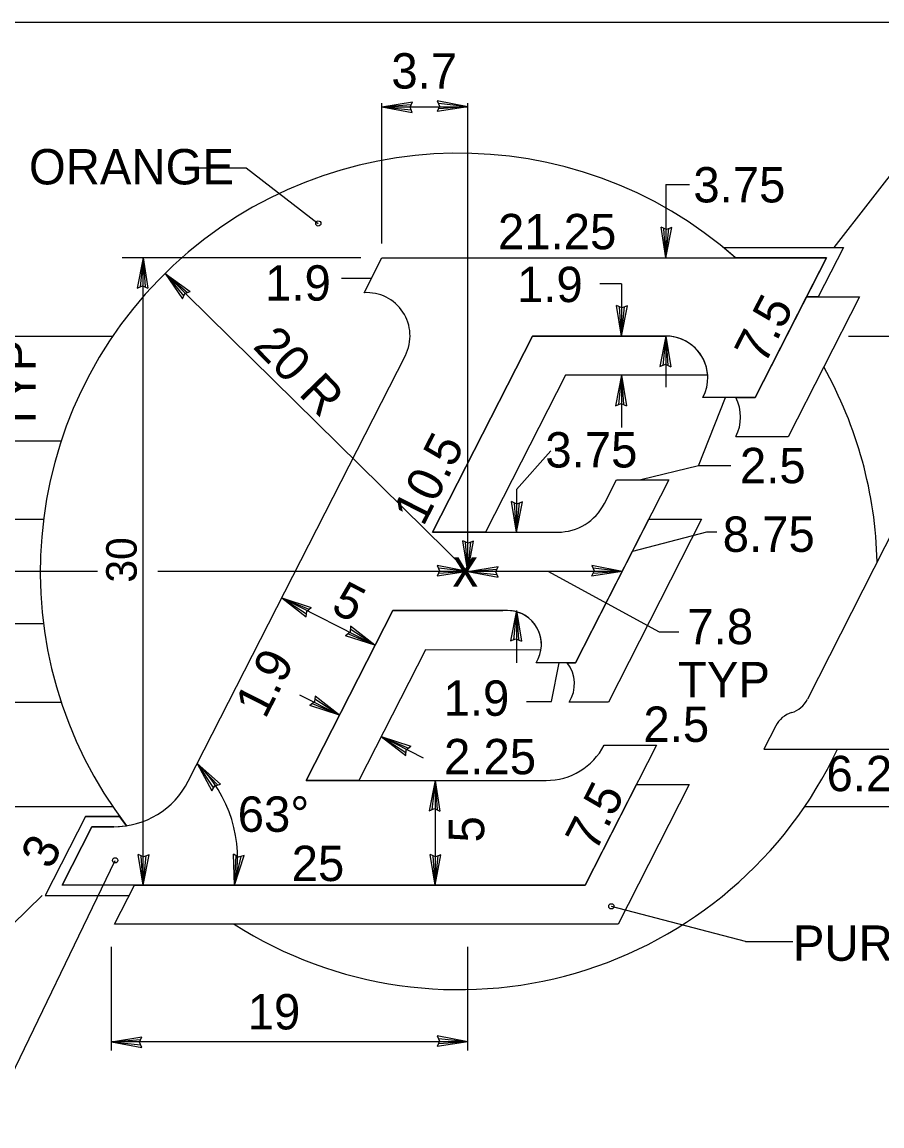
# Model space of a CAD drawing. Extents: x 10268197 to 10269179, y 2141503 to 2142677.
# Drawn here: x 10268467.86 to 10268484.88, y 2142149.08 to 2142170.94 of the extents above; entities that cross this region are included whole.
import ezdxf

# ---------------------------------------------------------------- set-up
doc = ezdxf.new("R2010")
doc.units = 0
for name, color, linetype in [('1', 7, 'Continuous'), ('2', 7, 'Continuous'), ('21', 7, 'Continuous'), ('3', 7, 'Continuous')]:
    doc.layers.add(name, color=color, linetype=linetype)

msp = doc.modelspace()

# ---------------------------------------------------------------- linework, layer by layer
at = {"layer": '1'}
for p, q in [((10268466.124, 2142170.939), (10268491.278, 2142170.939)), ((10268474.985, 2142169.263), (10268475.59, 2142169.359)), ((10268474.985, 2142166.558), (10268474.985, 2142169.336)), ((10268474.985, 2142169.263), (10268475.565, 2142169.304)), ((10268474.985, 2142169.263), (10268476.683, 2142169.263)), ((10268474.985, 2142169.263), (10268475.586, 2142169.147)), ((10268474.985, 2142169.263), (10268475.563, 2142169.203)), ((10268475.542, 2142169.254), (10268475.59, 2142169.359)), ((10268475.586, 2142169.147), (10268475.542, 2142169.254)), ((10268476.683, 2142160.063), (10268476.683, 2142169.336)), ((10268483.936, 2142166.474), (10268485.961, 2142169.092)), ((10268471.362, 2142168.055), (10268472.299, 2142168.055)), ((10268472.299, 2142168.055), (10268473.726, 2142166.952)), ((10268480.605, 2142167.724), (10268480.605, 2142166.274)), ((10268480.605, 2142167.724), (10268481.073, 2142167.724)), ((10268480.605, 2142166.274), (10268480.509, 2142166.879)), ((10268480.614, 2142166.831), (10268480.509, 2142166.879)), ((10268480.605, 2142166.274), (10268480.565, 2142166.854)), ((10268480.605, 2142166.274), (10268480.722, 2142166.875)), ((10268480.605, 2142166.274), (10268480.665, 2142166.852)), ((10268480.722, 2142166.875), (10268480.614, 2142166.831)), ((10268474.571, 2142166.274), (10268469.846, 2142166.274)), ((10268470.259, 2142166.274), (10268470.143, 2142165.672)), ((10268470.259, 2142166.274), (10268470.199, 2142165.695)), ((10268470.259, 2142153.853), (10268470.259, 2142166.274)), ((10268470.259, 2142166.274), (10268470.355, 2142165.668)), ((10268470.259, 2142166.274), (10268470.3, 2142165.694)), ((10268476.683, 2142160.063), (10268470.694, 2142165.963)), ((10268470.694, 2142165.963), (10268471.193, 2142165.607)), ((10268470.694, 2142165.963), (10268471.041, 2142165.457)), ((10268470.694, 2142165.963), (10268471.065, 2142165.514)), ((10268470.694, 2142165.963), (10268471.136, 2142165.585)), ((10268474.774, 2142165.86), (10268474.184, 2142165.86)), ((10268479.726, 2142165.756), (10268479.295, 2142165.756)), ((10268479.726, 2142165.756), (10268479.726, 2142164.721)), ((10268470.143, 2142165.672), (10268470.25, 2142165.717)), ((10268470.25, 2142165.717), (10268470.355, 2142165.668)), ((10268471.041, 2142165.457), (10268471.085, 2142165.565)), ((10268471.085, 2142165.565), (10268471.193, 2142165.607)), ((10268479.726, 2142164.721), (10268479.629, 2142165.326)), ((10268479.735, 2142165.278), (10268479.629, 2142165.326)), ((10268479.726, 2142164.721), (10268479.685, 2142165.301)), ((10268479.726, 2142164.721), (10268479.842, 2142165.323)), ((10268479.726, 2142164.721), (10268479.786, 2142165.299)), ((10268479.842, 2142165.323), (10268479.735, 2142165.278)), ((10268482.372, 2142163.504), (10268483.388, 2142165.497)), ((10268484.433, 2142165.497), (10268483.023, 2142162.73)), ((10268483.388, 2142165.497), (10268484.433, 2142165.497)), ((10268475.989, 2142160.84), (10268477.966, 2142164.721)), ((10268477.966, 2142164.721), (10268480.605, 2142164.721)), ((10268480.605, 2142164.721), (10268480.488, 2142164.119)), ((10268480.605, 2142164.721), (10268480.544, 2142164.142)), ((10268480.605, 2142164.721), (10268480.701, 2142164.115)), ((10268480.605, 2142164.721), (10268480.646, 2142164.142)), ((10268480.605, 2142164.721), (10268480.605, 2142163.71)), ((10268480.488, 2142164.119), (10268480.595, 2142164.164)), ((10268480.595, 2142164.164), (10268480.701, 2142164.115)), ((10268478.617, 2142163.945), (10268477.035, 2142160.84)), ((10268481.432, 2142163.945), (10268478.617, 2142163.945)), ((10268479.726, 2142163.945), (10268479.609, 2142163.343)), ((10268479.726, 2142163.945), (10268479.665, 2142163.366)), ((10268479.726, 2142163.945), (10268479.726, 2142162.91)), ((10268479.726, 2142163.945), (10268479.822, 2142163.339)), ((10268479.726, 2142163.945), (10268479.766, 2142163.365)), ((10268479.609, 2142163.343), (10268479.717, 2142163.387)), ((10268479.717, 2142163.387), (10268479.822, 2142163.339)), ((10268481.25, 2142162.153), (10268481.781, 2142163.507)), ((10268481.987, 2142163.504), (10268482.372, 2142163.504)), ((10268483.023, 2142162.73), (10268481.988, 2142162.73)), ((10268478.33, 2142162.452), (10268477.647, 2142161.682)), ((10268481.25, 2142162.153), (10268480.111, 2142161.875)), ((10268481.893, 2142162.153), (10268481.25, 2142162.153)), ((10268477.647, 2142161.682), (10268477.647, 2142160.84)), ((10268477.647, 2142160.84), (10268477.551, 2142161.444)), ((10268477.657, 2142161.397), (10268477.551, 2142161.444)), ((10268477.647, 2142160.84), (10268477.607, 2142161.419)), ((10268477.647, 2142160.84), (10268477.764, 2142161.441)), ((10268477.647, 2142160.84), (10268477.708, 2142161.418)), ((10268477.764, 2142161.441), (10268477.657, 2142161.397)), ((10268478.816, 2142158.252), (10268480.267, 2142161.098)), ((10268481.312, 2142161.098), (10268479.466, 2142157.475)), ((10268480.267, 2142161.098), (10268481.312, 2142161.098)), ((10268477.035, 2142160.84), (10268475.989, 2142160.84)), ((10268481.405, 2142160.84), (10268479.942, 2142160.46)), ((10268481.611, 2142160.84), (10268481.405, 2142160.84)), ((10268476.683, 2142160.063), (10268476.586, 2142160.668)), ((10268476.692, 2142160.621), (10268476.586, 2142160.668)), ((10268476.683, 2142160.063), (10268476.642, 2142160.643)), ((10268476.683, 2142160.063), (10268476.799, 2142160.664)), ((10268476.683, 2142160.063), (10268476.743, 2142160.641)), ((10268476.799, 2142160.664), (10268476.692, 2142160.621)), ((10268469.356, 2142160.063), (10268462.621, 2142160.063)), ((10268476.683, 2142160.063), (10268470.549, 2142160.063)), ((10268476.125, 2142160.073), (10268476.077, 2142159.967)), ((10268476.683, 2142160.063), (10268476.077, 2142159.967)), ((10268476.683, 2142160.063), (10268476.081, 2142160.18)), ((10268476.081, 2142160.18), (10268476.125, 2142160.073)), ((10268476.683, 2142160.063), (10268476.103, 2142160.023)), ((10268476.683, 2142160.063), (10268476.104, 2142160.124)), ((10268476.683, 2142160.063), (10268477.287, 2142160.159)), ((10268476.683, 2142160.063), (10268477.262, 2142160.104)), ((10268479.739, 2142160.063), (10268476.683, 2142160.063)), ((10268476.683, 2142160.063), (10268477.284, 2142159.947)), ((10268476.683, 2142160.063), (10268477.261, 2142160.003)), ((10268477.239, 2142160.054), (10268477.287, 2142160.159)), ((10268477.284, 2142159.947), (10268477.239, 2142160.054)), ((10268480.479, 2142158.858), (10268478.275, 2142160.063)), ((10268479.182, 2142160.073), (10268479.134, 2142159.967)), ((10268479.739, 2142160.063), (10268479.134, 2142159.967)), ((10268479.739, 2142160.063), (10268479.137, 2142160.18)), ((10268479.137, 2142160.18), (10268479.182, 2142160.073)), ((10268479.739, 2142160.063), (10268479.159, 2142160.023)), ((10268479.739, 2142160.063), (10268479.161, 2142160.124)), ((10268474.848, 2142158.599), (10268473.003, 2142159.54)), ((10268473.003, 2142159.54), (10268473.586, 2142159.35)), ((10268473.003, 2142159.54), (10268473.486, 2142159.162)), ((10268473.003, 2142159.54), (10268473.491, 2142159.223)), ((10268473.003, 2142159.54), (10268473.538, 2142159.313)), ((10268473.484, 2142155.923), (10268475.198, 2142159.287)), ((10268473.486, 2142159.162), (10268473.496, 2142159.278)), ((10268473.496, 2142159.278), (10268473.586, 2142159.35)), ((10268475.198, 2142159.287), (10268477.372, 2142159.28)), ((10268477.647, 2142159.287), (10268477.531, 2142158.685)), ((10268477.647, 2142159.287), (10268477.587, 2142158.708)), ((10268477.647, 2142159.287), (10268477.744, 2142158.681)), ((10268477.647, 2142159.287), (10268477.688, 2142158.707)), ((10268477.647, 2142159.287), (10268477.647, 2142158.252)), ((10268474.365, 2142158.976), (10268474.356, 2142158.861)), ((10268474.848, 2142158.599), (10268474.365, 2142158.976)), ((10268474.356, 2142158.861), (10268474.265, 2142158.788)), ((10268474.848, 2142158.599), (10268474.265, 2142158.788)), ((10268474.848, 2142158.599), (10268474.313, 2142158.826)), ((10268474.848, 2142158.599), (10268474.36, 2142158.916)), ((10268480.864, 2142158.858), (10268480.479, 2142158.858)), ((10268477.531, 2142158.685), (10268477.638, 2142158.73)), ((10268477.638, 2142158.73), (10268477.744, 2142158.681)), ((10268475.847, 2142158.509), (10268474.53, 2142155.923)), ((10268478.133, 2142158.501), (10268475.847, 2142158.509)), ((10268478.339, 2142157.489), (10268478.495, 2142158.252)), ((10268478.653, 2142158.252), (10268478.816, 2142158.252)), ((10268474.143, 2142157.216), (10268473.362, 2142157.615)), ((10268473.651, 2142157.478), (10268473.56, 2142157.405)), ((10268474.143, 2142157.216), (10268473.609, 2142157.443)), ((10268473.661, 2142157.594), (10268473.651, 2142157.478)), ((10268474.143, 2142157.216), (10268473.656, 2142157.533)), ((10268474.143, 2142157.216), (10268473.661, 2142157.594)), ((10268477.844, 2142157.489), (10268478.339, 2142157.489)), ((10268479.466, 2142157.475), (10268478.69, 2142157.475)), ((10268474.143, 2142157.216), (10268473.56, 2142157.405)), ((10268475.805, 2142156.368), (10268474.973, 2142156.792)), ((10268474.973, 2142156.792), (10268475.556, 2142156.603)), ((10268474.973, 2142156.792), (10268475.456, 2142156.416)), ((10268474.973, 2142156.792), (10268475.461, 2142156.476)), ((10268474.973, 2142156.792), (10268475.508, 2142156.566)), ((10268475.465, 2142156.531), (10268475.556, 2142156.603)), ((10268475.456, 2142156.416), (10268475.465, 2142156.531)), ((10268471.331, 2142156.257), (10268471.788, 2142155.849)), ((10268471.331, 2142156.257), (10268471.62, 2142155.717)), ((10268471.331, 2142156.257), (10268471.65, 2142155.77)), ((10268471.331, 2142156.257), (10268471.729, 2142155.834)), ((10268474.53, 2142155.923), (10268473.484, 2142155.923)), ((10268476.037, 2142155.923), (10268475.92, 2142155.322)), ((10268476.037, 2142155.923), (10268475.976, 2142155.345)), ((10268476.037, 2142155.923), (10268476.037, 2142153.853)), ((10268476.037, 2142155.923), (10268476.133, 2142155.317)), ((10268476.037, 2142155.923), (10268476.077, 2142155.343)), ((10268471.62, 2142155.717), (10268471.676, 2142155.819)), ((10268471.676, 2142155.819), (10268471.788, 2142155.849)), ((10268479.007, 2142153.853), (10268480.022, 2142155.843)), ((10268481.067, 2142155.843), (10268479.657, 2142153.076)), ((10268480.022, 2142155.843), (10268481.067, 2142155.843)), ((10268475.92, 2142155.322), (10268476.027, 2142155.366)), ((10268476.027, 2142155.366), (10268476.133, 2142155.317)), ((10268470.259, 2142153.853), (10268470.163, 2142154.458)), ((10268470.269, 2142154.41), (10268470.163, 2142154.458)), ((10268470.259, 2142153.853), (10268470.219, 2142154.432)), ((10268470.259, 2142153.853), (10268470.376, 2142154.454)), ((10268470.259, 2142153.853), (10268470.32, 2142154.431)), ((10268470.376, 2142154.454), (10268470.269, 2142154.41)), ((10268472.071, 2142153.853), (10268472.05, 2142154.465)), ((10268472.148, 2142154.404), (10268472.05, 2142154.465)), ((10268472.071, 2142153.853), (10268472.261, 2142154.436)), ((10268472.071, 2142153.853), (10268472.101, 2142154.433)), ((10268472.071, 2142153.853), (10268472.201, 2142154.419)), ((10268472.261, 2142154.436), (10268472.148, 2142154.404)), ((10268476.037, 2142153.853), (10268475.94, 2142154.458)), ((10268476.046, 2142154.41), (10268475.94, 2142154.458)), ((10268476.037, 2142153.853), (10268475.996, 2142154.432)), ((10268476.037, 2142153.853), (10268476.153, 2142154.454)), ((10268476.037, 2142153.853), (10268476.097, 2142154.431)), ((10268476.153, 2142154.454), (10268476.046, 2142154.41)), ((10268467.17, 2142149.083), (10268469.706, 2142154.341)), ((10268469.692, 2142153.076), (10268470.088, 2142153.853)), ((10268470.088, 2142153.853), (10268479.007, 2142153.853)), ((10268466.668, 2142152.098), (10268468.262, 2142153.645)), ((10268482.183, 2142152.735), (10268479.525, 2142153.43)), ((10268479.657, 2142153.076), (10268469.692, 2142153.076)), ((10268469.632, 2142150.576), (10268469.632, 2142152.632)), ((10268476.683, 2142150.576), (10268476.683, 2142152.632)), ((10268482.183, 2142152.735), (10268483.12, 2142152.735)), ((10268476.683, 2142150.751), (10268469.632, 2142150.751))]:
    msp.add_line(p, q, dxfattribs=at)
msp.add_lwpolyline([(10268481.746, 2142166.474), (10268484.118, 2142166.474), (10268483.621, 2142165.497), (10268483.388, 2142165.497), (10268483.784, 2142166.274), (10268481.982, 2142166.274)], close=True, dxfattribs=at)
for centre in [(10268473.726, 2142166.952), (10268469.706, 2142154.342), (10268479.525, 2142153.431)]:
    msp.add_circle(centre, 0.0518, dxfattribs=at)
for centre, radius, start, end in [((10268480.605, 2142163.893), 0.828, 3.5833, 90), ((10268481.255, 2142163.117), 0.828, 332.2089, 27.9127), ((10268477.469, 2142158.614), 0.673, 350.3502, 98.3344), ((10268478.123, 2142157.838), 0.673, 327.421, 37.9799), ((10268469.54, 2142154.39), 2.588, 348.03, 46.2026)]:
    msp.add_arc(centre, radius, start, end, dxfattribs=at)
at = {"layer": '2'}
for p, q in [((10268481.746, 2142166.474), (10268484.118, 2142166.474)), ((10268484.118, 2142166.474), (10268483.621, 2142165.497)), ((10268474.632, 2142165.58), (10268474.985, 2142166.274)), ((10268474.985, 2142166.274), (10268483.784, 2142166.274)), ((10268483.784, 2142166.274), (10268482.373, 2142163.507)), ((10268482.372, 2142163.504), (10268483.388, 2142165.497)), ((10268484.433, 2142165.497), (10268483.023, 2142162.73)), ((10268483.388, 2142165.497), (10268484.433, 2142165.497)), ((10268466.124, 2142164.721), (10268469.658, 2142164.721)), ((10268477.966, 2142164.721), (10268475.989, 2142160.84)), ((10268475.989, 2142160.84), (10268477.966, 2142164.721)), ((10268480.605, 2142164.721), (10268477.966, 2142164.721)), ((10268477.966, 2142164.721), (10268480.605, 2142164.721)), ((10268484.215, 2142164.721), (10268513.738, 2142164.721)), ((10268471.154, 2142155.91), (10268475.449, 2142164.34)), ((10268478.617, 2142163.945), (10268477.035, 2142160.84)), ((10268481.432, 2142163.945), (10268478.617, 2142163.945)), ((10268482.373, 2142163.507), (10268481.338, 2142163.507)), ((10268481.987, 2142163.504), (10268482.372, 2142163.504)), ((10268483.023, 2142162.73), (10268481.988, 2142162.73)), ((10268465.07, 2142162.651), (10268468.638, 2142162.651)), ((10268485.97, 2142162.597), (10268483.408, 2142157.53)), ((10268480.662, 2142161.875), (10268478.816, 2142158.252)), ((10268479.387, 2142161.405), (10268479.627, 2142161.875)), ((10268479.627, 2142161.875), (10268480.662, 2142161.875)), ((10268464.278, 2142161.098), (10268468.289, 2142161.098)), ((10268478.816, 2142158.252), (10268480.267, 2142161.098)), ((10268481.312, 2142161.098), (10268479.466, 2142157.475)), ((10268480.267, 2142161.098), (10268481.312, 2142161.098)), ((10268475.989, 2142160.84), (10268478.465, 2142160.84)), ((10268477.035, 2142160.84), (10268475.989, 2142160.84)), ((10268475.198, 2142159.287), (10268473.484, 2142155.923)), ((10268473.484, 2142155.923), (10268475.198, 2142159.287)), ((10268477.47, 2142159.287), (10268475.198, 2142159.287)), ((10268475.198, 2142159.287), (10268477.372, 2142159.28)), ((10268463.223, 2142159.028), (10268468.289, 2142159.028)), ((10268475.847, 2142158.509), (10268474.53, 2142155.923)), ((10268478.133, 2142158.501), (10268475.847, 2142158.509)), ((10268478.816, 2142158.252), (10268478.037, 2142158.252)), ((10268478.653, 2142158.252), (10268478.816, 2142158.252)), ((10268462.432, 2142157.475), (10268468.638, 2142157.475)), ((10268479.466, 2142157.475), (10268478.69, 2142157.475)), ((10268482.778, 2142157.004), (10268482.545, 2142156.544)), ((10268480.417, 2142156.619), (10268479.007, 2142153.853)), ((10268479.381, 2142156.619), (10268480.417, 2142156.619)), ((10268482.545, 2142156.544), (10268485.133, 2142156.544)), ((10268473.484, 2142155.923), (10268478.234, 2142155.923)), ((10268474.53, 2142155.923), (10268473.484, 2142155.923)), ((10268479.007, 2142153.853), (10268480.022, 2142155.843)), ((10268481.067, 2142155.843), (10268479.657, 2142153.076)), ((10268480.022, 2142155.843), (10268481.067, 2142155.843)), ((10268461.378, 2142155.405), (10268469.658, 2142155.405)), ((10268483.351, 2142155.405), (10268508.992, 2142155.405)), ((10268469.116, 2142155.213), (10268468.319, 2142153.645)), ((10268469.116, 2142155.213), (10268469.793, 2142155.213)), ((10268468.657, 2142153.853), (10268469.244, 2142155.006)), ((10268469.244, 2142155.006), (10268468.657, 2142153.853)), ((10268469.244, 2142155.006), (10268469.679, 2142155.006)), ((10268469.678, 2142155.006), (10268469.244, 2142155.006)), ((10268479.007, 2142153.853), (10268468.657, 2142153.853)), ((10268469.692, 2142153.076), (10268470.088, 2142153.853)), ((10268470.088, 2142153.853), (10268479.007, 2142153.853)), ((10268468.319, 2142153.645), (10268469.982, 2142153.645)), ((10268479.657, 2142153.076), (10268469.692, 2142153.076))]:
    msp.add_line(p, q, dxfattribs=at)
for centre, radius, start, end in [((10268476.505, 2142160.063), 8.281, 48.5904, 217.4725), ((10268474.688, 2142164.728), 0.854, 332.9998, 93.8045), ((10268480.605, 2142163.893), 0.828, 332.2089, 90), ((10268480.605, 2142163.893), 0.828, 3.5833, 90), ((10268476.505, 2142160.063), 8.281, 1.2967, 29.2778), ((10268481.255, 2142163.117), 0.828, 332.2089, 27.9127), ((10268478.465, 2142161.875), 1.035, 270, 332.9883), ((10268477.469, 2142158.614), 0.673, 350.3502, 98.3344), ((10268477.469, 2142158.614), 0.673, 327.421, 90), ((10268478.123, 2142157.838), 0.673, 327.421, 37.9799), ((10268478.234, 2142157.217), 1.294, 270, 332.5096), ((10268476.505, 2142160.063), 8.281, 237.5383, 334.8493), ((10268469.678, 2142156.662), 1.656, 270, 332.9991)]:
    msp.add_arc(centre, radius, start, end, dxfattribs=at)
for centre, start_param, end_param in [((10268482.946, 2142157.767), 0.286787, 1.099486), ((10268483.239, 2142156.767), 3.428379, 4.240701)]:
    msp.add_ellipse(centre, major_axis=(0, -0.521), ratio=0.992614, start_param=start_param, end_param=end_param, dxfattribs=at)
at = {"layer": '21'}
for p, q in [((10268476.125, 2142169.273), (10268476.077, 2142169.167)), ((10268476.683, 2142169.263), (10268476.077, 2142169.167)), ((10268476.683, 2142169.263), (10268476.081, 2142169.38)), ((10268476.081, 2142169.38), (10268476.125, 2142169.273)), ((10268476.683, 2142169.263), (10268476.103, 2142169.223)), ((10268476.683, 2142169.263), (10268476.104, 2142169.324)), ((10268476.683, 2142150.751), (10268476.081, 2142150.867)), ((10268476.081, 2142150.867), (10268476.125, 2142150.76)), ((10268469.632, 2142150.751), (10268470.237, 2142150.847)), ((10268469.632, 2142150.751), (10268470.212, 2142150.792)), ((10268469.632, 2142150.751), (10268470.234, 2142150.634)), ((10268469.632, 2142150.751), (10268470.211, 2142150.691)), ((10268470.189, 2142150.742), (10268470.237, 2142150.847)), ((10268470.234, 2142150.634), (10268470.189, 2142150.742)), ((10268476.125, 2142150.76), (10268476.077, 2142150.655)), ((10268476.683, 2142150.751), (10268476.077, 2142150.655)), ((10268476.683, 2142150.751), (10268476.103, 2142150.71)), ((10268476.683, 2142150.751), (10268476.104, 2142150.811))]:
    msp.add_line(p, q, dxfattribs=at)
at = {"layer": '3'}
msp.add_lwpolyline([(10268469.793, 2142155.213), (10268469.116, 2142155.213), (10268468.319, 2142153.645), (10268469.982, 2142153.645), (10268470.088, 2142153.853), (10268468.657, 2142153.853), (10268469.244, 2142155.006), (10268469.679, 2142155.006), (10268469.933, 2142155.026)], close=True, dxfattribs=at)

# ---------------------------------------------------------------- texts
at = {"layer": '1'}
for s, height, p in [('3.7', 0.7, (10268475.172, 2142169.623)), ('ORANGE', 0.7, (10268468, 2142167.725)), ('3.75', 0.7, (10268481.148, 2142167.368)), ('21.25', 0.7, (10268477.281, 2142166.441)), ('1.9', 0.7, (10268472.673, 2142165.424)), ('1.9', 0.7, (10268477.658, 2142165.395)), ('3.75', 0.7, (10268478.219, 2142162.12)), ('2.5', 0.7, (10268482.069, 2142161.809)), ('8.75', 0.7, (10268481.729, 2142160.45)), ('x', 0.755, (10268476.383, 2142159.762)), ('7.8', 0.7, (10268481.029, 2142158.621)), ('TYP', 0.7, (10268480.844, 2142157.571)), ('1.9', 0.7, (10268476.205, 2142157.204)), ('2.5', 0.7, (10268480.16, 2142156.687)), ('2.25', 0.7, (10268476.214, 2142156.046)), ('6.25', 0.7, (10268483.782, 2142155.711)), ('63°', 0.7, (10268472.131, 2142154.907)), ('25', 0.7, (10268473.199, 2142153.932)), ('PURPLE', 0.7, (10268483.118, 2142152.353)), ('19', 0.7, (10268472.328, 2142150.994))]:
    msp.add_text(s, height=height, dxfattribs=at).set_placement(p)
for s, height, rotation, p in [('7.5', 0.7, 63, (10268482.556, 2142164.136)), ('20 R', 0.7, 314.1812, (10268472.409, 2142164.501)), ('TYP', 0.7, 90, (10268468.135, 2142162.831)), ('10.5', 0.7, 63.0402, (10268475.804, 2142160.935)), ('30', 0.6037, 90, (10268470.132, 2142159.841)), ('5', 0.7, 332.9866, (10268473.951, 2142159.272)), ('1.9', 0.7, 63.0402, (10268472.675, 2142157.123)), ('7.5', 0.7, 63, (10268479.209, 2142154.486)), ('5', 0.7, 90, (10268477.009, 2142154.696)), ('3', 0.7, 63, (10268468.433, 2142154.138))]:
    msp.add_text(s, height=height, rotation=rotation, dxfattribs=at).set_placement(p)

doc.saveas('drawing.dxf')
